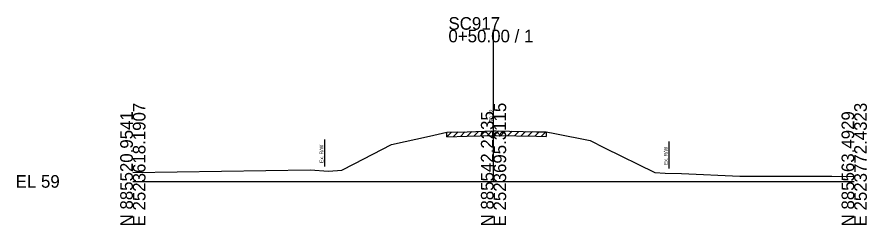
# Model space of a CAD drawing. Extents: x -26 to 218, y -10 to 12021.
# Drawn here: x -25.7 to 162.8, y 490.3 to 536.5 of the extents above; entities that cross this region are included whole.
import ezdxf

# ---------------------------------------------------------------- set-up
doc = ezdxf.new("R2010")
doc.units = 0
for name, color, linetype in [('RD_GPK_XS_Cell', 7, 'Continuous'), ('RD_XS_ExGround', 7, 'Continuous'), ('RD_XS_ExPaveRet', 7, 'Continuous'), ('RD_XS_ExRW', 7, 'Continuous'), ('RD_XS_TX_Elev_EX', 7, 'Continuous')]:
    doc.layers.add(name, color=color, linetype=linetype)

msp = doc.modelspace()

# ---------------------------------------------------------------- linework, layer by layer
at = {"layer": 'RD_GPK_XS_Cell'}
for p, q in [((80, 500), (80, 533.71)), ((0, 500), (80, 500)), ((80, 500), (160, 500))]:
    msp.add_line(p, q, dxfattribs=at)
at = {"layer": 'RD_XS_ExGround'}
for p, q in [((69.64, 510.91), (74.18, 511.04)), ((74.18, 511.04), (80, 511.22)), ((80, 511.22), (80.61, 511.24)), ((80.61, 511.24), (89.57, 511.05)), ((89.57, 511.05), (91.67, 511)), ((91.67, 511), (93.61, 510.65)), ((57.39, 508.2), (65.83, 510.09)), ((65.83, 510.09), (69.64, 510.91)), ((93.61, 510.65), (101.42, 509.11)), ((101.42, 509.11), (104.65, 507.43)), ((49.09, 503.89), (57.39, 508.2)), ((104.65, 507.43), (115.77, 501.95)), ((46.37, 502.47), (49.09, 503.89)), ((0, 502), (39.31, 502.56)), ((39.31, 502.56), (43.4, 502.25)), ((43.4, 502.25), (46.37, 502.47)), ((115.77, 501.95), (118.1, 501.87)), ((118.1, 501.87), (121.67, 501.79)), ((121.67, 501.79), (134.62, 501.17)), ((134.62, 501.17), (155.01, 501.19)), ((155.01, 501.19), (160, 501.1))]:
    msp.add_line(p, q, dxfattribs=at)
at = {"layer": 'RD_XS_ExPaveRet'}
for p, q in [((69.64, 509.91), (70.67, 510.94)), ((71.14, 509.96), (72.17, 510.99)), ((72.64, 510), (73.67, 511.03)), ((74.14, 510.04), (75.17, 511.07)), ((75.64, 510.09), (76.67, 511.12)), ((77.14, 510.13), (78.17, 511.16)), ((78.64, 510.18), (79.67, 511.21)), ((80.14, 510.22), (81.14, 511.22)), ((81.64, 510.21), (82.62, 511.19)), ((83.14, 510.18), (84.12, 511.16)), ((84.64, 510.15), (85.62, 511.13)), ((86.14, 510.12), (87.12, 511.1)), ((87.64, 510.09), (88.62, 511.07)), ((89.14, 510.06), (90.12, 511.04)), ((90.64, 510.02), (91.62, 511)), ((91.67, 511), (91.67, 510)), ((69.64, 509.91), (69.64, 510.91)), ((69.64, 509.91), (74.18, 510.04)), ((74.18, 510.04), (80, 510.22)), ((80, 510.22), (80.61, 510.24)), ((80.61, 510.24), (89.57, 510.05)), ((89.57, 510.05), (91.67, 510))]:
    msp.add_line(p, q, dxfattribs=at)
at = {"layer": 'RD_XS_ExRW'}
for p, q in [((42.5, 509.32), (42.5, 503.32)), ((118.86, 508.85), (118.86, 502.85))]:
    msp.add_line(p, q, dxfattribs=at)

# ---------------------------------------------------------------- texts
at = {"layer": 'RD_GPK_XS_Cell'}
for s, p in [('SC917', (70, 533.71)), ('0+50.00 / 1', (70, 530.91)), ('EL 59', (-26, 498.6))]:
    msp.add_text(s, height=2.8, dxfattribs=at).set_placement(p)
for s, p in [('E 2523618.1907', (2.8, 490)), ('E 2523695.3115', (82.8, 490)), ('E 2523772.4323', (162.8, 490)), ('N 885520.9541', (0, 490)), ('N 885542.2235', (80, 490)), ('N 885563.4929', (160, 490))]:
    msp.add_text(s, height=2.8, rotation=90, dxfattribs=at).set_placement(p)
at = {"layer": 'RD_XS_ExRW'}
for p in [(42.25, 504.1), (118.61, 503.64)]:
    msp.add_text('Ex. R/W ', height=0.8, rotation=90, dxfattribs=at).set_placement(p)
at = {"layer": 'RD_XS_TX_Elev_EX'}
msp.add_text('70.22', height=0.8, rotation=90, dxfattribs=at).set_placement((79.9, 513.22))

doc.saveas('drawing.dxf')
